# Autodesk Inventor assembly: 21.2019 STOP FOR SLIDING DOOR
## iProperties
Created: 2013-02
Part Number: 21.2019 STOP FOR SLIDING DOOR
Document SubType Name: Assembly
Designer: Administrator
Author: Administrator
